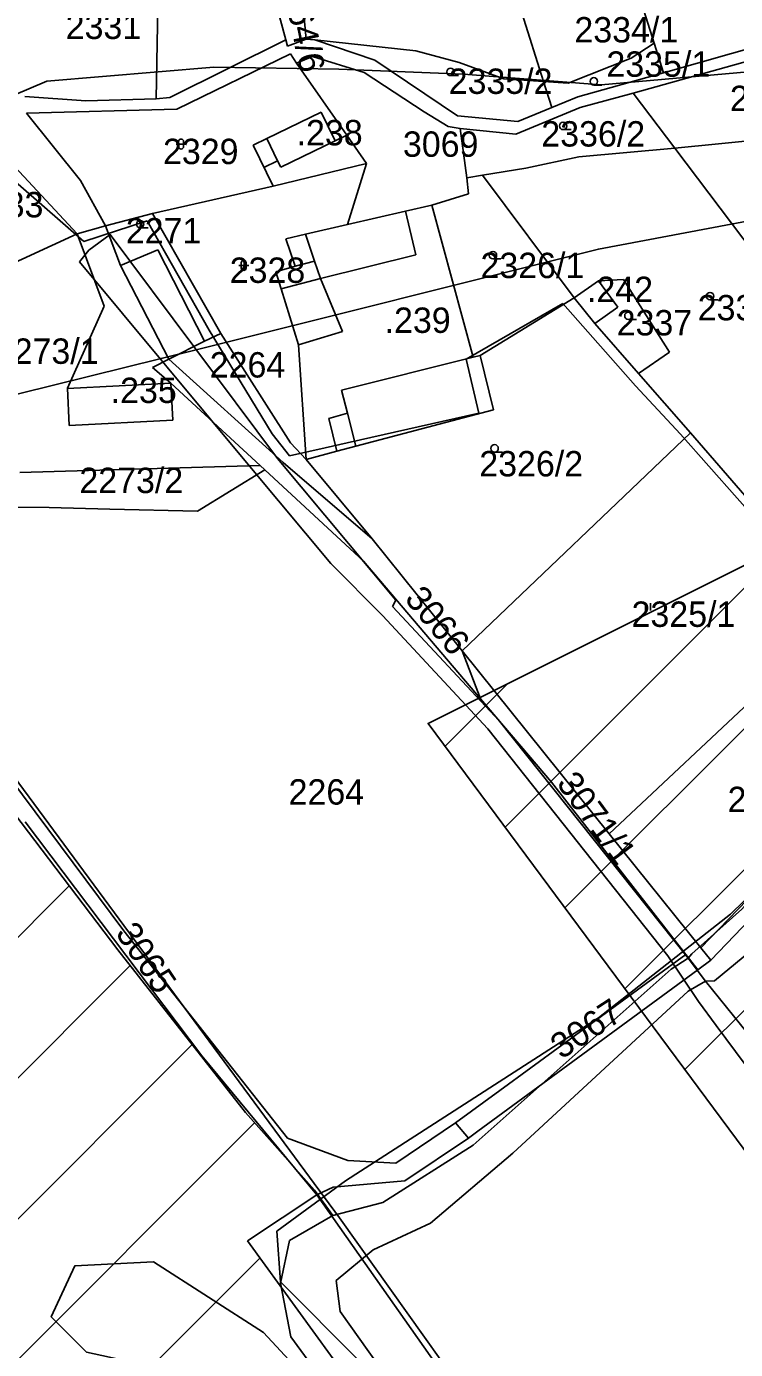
# Model space of a CAD drawing. Extents: x -564810 to -550519, y -1045831 to -1034011.
# Drawn here: x -553011.6 to -552869.1, y -1036898.7 to -1036632.8 of the extents above; entities that cross this region are included whole.
import ezdxf

# ---------------------------------------------------------------- set-up
doc = ezdxf.new("R2010")
doc.units = 0
for name, color, linetype in [('KN stav', 7, 'Continuous'), ('Lesní porost', 7, 'Continuous'), ('Obvod KPU', 7, 'Continuous'), ('Odvodněné plochy', 7, 'Continuous'), ('Parcelní čísla', 7, 'Continuous'), ('Polní cesty stavající', 7, 'Continuous'), ('přeložka st silnice', 7, 'Continuous'), ('STG', 7, 'Continuous'), ('vodní toky', 7, 'Continuous'), ('Vrstva 22', 7, 'Continuous'), ('Vrstva 33', 7, 'Continuous'), ('Vrstva 4', 7, 'Continuous'), ('Vrstva 5', 7, 'Continuous'), ('zamokř ploch', 7, 'Continuous')]:
    doc.layers.add(name, color=color, linetype=linetype)

msp = doc.modelspace()

# ---------------------------------------------------------------- linework, layer by layer
at = {"layer": 'KN stav'}
for p, q in [((-552957.26, -1036615.94), (-552955.38, -1036635.35)), ((-552963.64, -1036619.89), (-552959.48, -1036635.45)), ((-552889.16, -1036624.42), (-552885.49, -1036636.1)), ((-552985.17, -1036628.73), (-552985.52, -1036647.32)), ((-552912.09, -1036630.06), (-552907.71, -1036643.85)), ((-552959.48, -1036635.45), (-552982.76, -1036647.02)), ((-552959.15, -1036636.7), (-552959.48, -1036635.45)), ((-552955.38, -1036635.35), (-552959.15, -1036636.7)), ((-552953.69, -1036635.47), (-552955.38, -1036635.35)), ((-552933.36, -1036637.65), (-552953.69, -1036635.47)), ((-552941.59, -1036639.51), (-552953.69, -1036635.47)), ((-552885.49, -1036636.1), (-552890.09, -1036639.11)), ((-552885.49, -1036636.1), (-552883.61, -1036642.07)), ((-552861.75, -1036635.89), (-552883.61, -1036642.07)), ((-552981.4, -1036649.36), (-552958.55, -1036638.25)), ((-552958.55, -1036638.25), (-552957.33, -1036640.15)), ((-552957.33, -1036640.15), (-552954.14, -1036638.82)), ((-552954.14, -1036638.82), (-552943.77, -1036642.01)), ((-552925, -1036650.72), (-552941.59, -1036639.51)), ((-552924.65, -1036639.99), (-552933.36, -1036637.65)), ((-552915.7, -1036643.3), (-552924.65, -1036639.99)), ((-552890.09, -1036639.11), (-552902.79, -1036644.19)), ((-552889.68, -1036646.16), (-552862.2, -1036638.49)), ((-552957.33, -1036640.15), (-552947.24, -1036654.58)), ((-552943.77, -1036642.01), (-552931.72, -1036649.92)), ((-552883.61, -1036642.07), (-552900.83, -1036646.94)), ((-552907.71, -1036643.85), (-552915.7, -1036643.3)), ((-552907.71, -1036643.85), (-552906.06, -1036649.07)), ((-552902.79, -1036644.19), (-552907.71, -1036643.85)), ((-552999.69, -1036647.72), (-553011.94, -1036646.87)), ((-552985.52, -1036647.32), (-552999.69, -1036647.72)), ((-552982.76, -1036647.02), (-552985.52, -1036647.32)), ((-552900.83, -1036646.94), (-552906.06, -1036649.07)), ((-552900.36, -1036649.04), (-552889.68, -1036646.16)), ((-552889.68, -1036646.16), (-552881.33, -1036657.22)), ((-553011.59, -1036650.17), (-552981.4, -1036649.36)), ((-553000.75, -1036663.71), (-553011.59, -1036650.17)), ((-552952.39, -1036649.97), (-552963.32, -1036655.27)), ((-552949.6, -1036655.73), (-552952.39, -1036649.97)), ((-552931.72, -1036649.92), (-552926.89, -1036652.9)), ((-552913.26, -1036654.38), (-552900.36, -1036649.04)), ((-552906.06, -1036649.07), (-552912.9, -1036651.85)), ((-552926.89, -1036652.9), (-552924.46, -1036653.28)), ((-552912.9, -1036651.85), (-552925, -1036650.72)), ((-552924.46, -1036653.28), (-552923.15, -1036663.19)), ((-552924.46, -1036653.28), (-552913.26, -1036654.38)), ((-552963.32, -1036655.27), (-552966.06, -1036656.6)), ((-552947.24, -1036654.58), (-552949.6, -1036655.73)), ((-552947.24, -1036654.58), (-552943.26, -1036660.28)), ((-552853.82, -1036654.46), (-552881.33, -1036657.22)), ((-553017.54, -1036657.15), (-553001.41, -1036674.42)), ((-553001.41, -1036674.42), (-553017.54, -1036657.15)), ((-552966.06, -1036656.6), (-552962.05, -1036664.87)), ((-552881.33, -1036657.22), (-552900.64, -1036658.94)), ((-552881.33, -1036657.22), (-552855.3, -1036691.72)), ((-552962.05, -1036664.87), (-552943.26, -1036660.28)), ((-552943.26, -1036660.28), (-552947.09, -1036672.57)), ((-552911.26, -1036661.27), (-552919.98, -1036662.68)), ((-552900.64, -1036658.94), (-552911.26, -1036661.27)), ((-552995.74, -1036672.81), (-553000.75, -1036663.71)), ((-552923.15, -1036663.19), (-552919.98, -1036662.68)), ((-552923.15, -1036663.19), (-552922.82, -1036666.42)), ((-552919.98, -1036662.68), (-552901.58, -1036687.28)), ((-552962.05, -1036664.87), (-552986.29, -1036670.37)), ((-552922.82, -1036666.42), (-552930.17, -1036668.66)), ((-552935.45, -1036669.88), (-552930.17, -1036668.66)), ((-552930.17, -1036668.66), (-552921.84, -1036699.25)), ((-552986.29, -1036670.37), (-552995.74, -1036672.81)), ((-552986.29, -1036670.37), (-552972.56, -1036694.45)), ((-552947.09, -1036672.57), (-552935.45, -1036669.88)), ((-553001.41, -1036674.42), (-553034.02, -1036689.47)), ((-553034.02, -1036689.47), (-553001.41, -1036674.42)), ((-553001.41, -1036674.42), (-552995.74, -1036672.81)), ((-553001.41, -1036674.42), (-552995.95, -1036689.01)), ((-552995.74, -1036672.81), (-552992.72, -1036680.83)), ((-552955.54, -1036674.52), (-552959.47, -1036675.43)), ((-552947.09, -1036672.57), (-552955.54, -1036674.52)), ((-552959.47, -1036675.43), (-552957.61, -1036680.91)), ((-552992.72, -1036680.83), (-552985.21, -1036677.67)), ((-552985.21, -1036677.67), (-552975.8, -1036695.99)), ((-552957.61, -1036680.91), (-552961.47, -1036682.1)), ((-552961.47, -1036682.1), (-552960.41, -1036685.5)), ((-552896.68, -1036683.9), (-552901.58, -1036687.28)), ((-552891.64, -1036683.61), (-552896.68, -1036683.9)), ((-552896.68, -1036683.9), (-552892.78, -1036689.18)), ((-552882.38, -1036698.21), (-552891.64, -1036683.61)), ((-552960.41, -1036685.5), (-552956.92, -1036696.74)), ((-552920.46, -1036698.9), (-552901.58, -1036687.28)), ((-552901.58, -1036687.28), (-552897.39, -1036692.45)), ((-552995.95, -1036689.01), (-553003.37, -1036705.45)), ((-552892.78, -1036689.18), (-552897.39, -1036692.45)), ((-552897.39, -1036692.45), (-552888.64, -1036702.49)), ((-552972.56, -1036694.45), (-552975.8, -1036695.99)), ((-552958.52, -1036716.43), (-552972.56, -1036694.45)), ((-552975.8, -1036695.99), (-552982.97, -1036699.63)), ((-552956.92, -1036696.74), (-552955.37, -1036719.76)), ((-552888.64, -1036702.49), (-552882.38, -1036698.21)), ((-552982.97, -1036699.63), (-552986.24, -1036701.29)), ((-552982.97, -1036699.63), (-552959.99, -1036720.4)), ((-552921.84, -1036699.25), (-552920.46, -1036698.9)), ((-552920.46, -1036698.9), (-552917.74, -1036709.8)), ((-552986.24, -1036701.29), (-552982.56, -1036704.47)), ((-552888.64, -1036702.49), (-552878.21, -1036714.46)), ((-553003.37, -1036705.45), (-553003, -1036712.94)), ((-552982.19, -1036711.9), (-552982.56, -1036704.47)), ((-552982.56, -1036704.47), (-552964.61, -1036721.02)), ((-552917.74, -1036709.8), (-552945.39, -1036717.12)), ((-553003, -1036712.94), (-552982.19, -1036711.9)), ((-552955.37, -1036719.76), (-552958.52, -1036716.43)), ((-552878.21, -1036714.46), (-552924.04, -1036758.24)), ((-552878.21, -1036714.46), (-552863.3, -1036731.56)), ((-552949.23, -1036718.14), (-552955.37, -1036719.76)), ((-552942.13, -1036735.71), (-552955.37, -1036719.76)), ((-552945.39, -1036717.12), (-552949.23, -1036718.14)), ((-552964.61, -1036721.02), (-553012.94, -1036722.42)), ((-552963.73, -1036721.84), (-552977.2, -1036730.2)), ((-552963.73, -1036721.84), (-552964.61, -1036721.02)), ((-552943.85, -1036740.22), (-552963.73, -1036721.84)), ((-552959.99, -1036720.4), (-552942.13, -1036735.71)), ((-553035.83, -1036729.19), (-553007, -1036729.44)), ((-552994.87, -1036729.75), (-553007, -1036729.44)), ((-552977.2, -1036730.2), (-552994.87, -1036729.75)), ((-552942.13, -1036735.71), (-552924.04, -1036758.24)), ((-552920.37, -1036767.87), (-552943.85, -1036740.22)), ((-553044.87, -1036743.82), (-552992.06, -1036814.49)), ((-552847.39, -1036750.74), (-552894.52, -1036795.01)), ((-552924.04, -1036758.24), (-552920.37, -1036767.87)), ((-552924.04, -1036758.24), (-552894.52, -1036795.01)), ((-552906.11, -1036784.67), (-552920.37, -1036767.87)), ((-552879.12, -1036819.3), (-552906.11, -1036784.67)), ((-553011.86, -1036792.61), (-552976.39, -1036839.66)), ((-552976.39, -1036839.66), (-553011.86, -1036792.61)), ((-552894.52, -1036795.01), (-552876.14, -1036817.91)), ((-552854.93, -1036796), (-552876.14, -1036817.91)), ((-552854.06, -1036799.49), (-552874.11, -1036820.43)), ((-552992.06, -1036814.49), (-552959.16, -1036856.18)), ((-552876.14, -1036817.91), (-552874.11, -1036820.43)), ((-552916.49, -1036846.59), (-552879.12, -1036819.3)), ((-552879.12, -1036819.3), (-552876.74, -1036822.36)), ((-552874.11, -1036820.43), (-552876.74, -1036822.36)), ((-552876.74, -1036822.36), (-552920.89, -1036854.79)), ((-552976.39, -1036839.66), (-552953.24, -1036867.58)), ((-552953.24, -1036867.58), (-552976.39, -1036839.66)), ((-552925.41, -1036853.11), (-552916.49, -1036846.59)), ((-552937.36, -1036861.22), (-552925.41, -1036853.11)), ((-552925.41, -1036853.11), (-552922.78, -1036856.18)), ((-552920.89, -1036854.79), (-552922.78, -1036856.18)), ((-552959.16, -1036856.18), (-552947, -1036860.67)), ((-552922.78, -1036856.18), (-552935.6, -1036864.73)), ((-552947, -1036860.67), (-552937.36, -1036861.22)), ((-552935.6, -1036864.73), (-552949.96, -1036866.05)), ((-552953.24, -1036867.58), (-552967.16, -1036876.79)), ((-552967.16, -1036876.79), (-552953.24, -1036867.58)), ((-552949.96, -1036866.05), (-552953.24, -1036867.58)), ((-552953.24, -1036867.58), (-552842.6, -1037024.79)), ((-552967.16, -1036876.79), (-552909.89, -1036955.71)), ((-552909.89, -1036955.71), (-552967.16, -1036876.79))]:
    msp.add_line(p, q, dxfattribs=at)
at = {"layer": 'Lesní porost'}
for p, q in [((-553082.6, -1036885.05), (-553003, -1036805.46)), ((-553071.01, -1036901.75), (-552990.73, -1036821.47)), ((-553059.41, -1036918.44), (-552978.32, -1036837.34)), ((-553047.82, -1036935.13), (-552965.78, -1036853.08)), ((-553036.23, -1036951.82), (-552964.65, -1036880.24))]:
    msp.add_line(p, q, dxfattribs=at)
msp.add_lwpolyline([(-553146.64, -1036727.62), (-553139.68, -1036718.33), (-553129.51, -1036716.88), (-553121.51, -1036717.92), (-553113.12, -1036715.47), (-553098.36, -1036708.87), (-553083.05, -1036699.3), (-553078.09, -1036714.1), (-553071.17, -1036716.95), (-553043.41, -1036752.8), (-553036.17, -1036762.13), (-553020.94, -1036781.92), (-552993.21, -1036818.31), (-552967.61, -1036851.02), (-552953.72, -1036866.65), (-552950.02, -1036871.7), (-552958.74, -1036876.77), (-552960.54, -1036885.34), (-552958.5, -1036896.1), (-552948.99, -1036909.12)], dxfattribs=at)
at = {"layer": 'Obvod KPU'}
for p, q in [((-553000.04, -1036675.95), (-553018.55, -1036659.94)), ((-552987.32, -1036671.82), (-553000.04, -1036675.95)), ((-552974.88, -1036693.82), (-552987.32, -1036671.82)), ((-552903.86, -1036688.45), (-552923.24, -1036699.61)), ((-552889.25, -1036705), (-552903.86, -1036688.45)), ((-552962.23, -1036714.66), (-552974.88, -1036693.82)), ((-552923.24, -1036699.61), (-552920.71, -1036710.45)), ((-552880.17, -1036714.7), (-552889.25, -1036705)), ((-552920.71, -1036710.45), (-552947.16, -1036716.46)), ((-552958.74, -1036719.05), (-552962.23, -1036714.66)), ((-552947.16, -1036716.46), (-552951.58, -1036717.43)), ((-552861.65, -1036735.71), (-552880.17, -1036714.7)), ((-552951.58, -1036717.43), (-552958.74, -1036719.05))]:
    msp.add_line(p, q, dxfattribs=at)
at = {"layer": 'Odvodněné plochy'}
msp.add_lwpolyline([(-552687.96, -1037100.5), (-552930.89, -1036772.83), (-552794.7, -1036704.72), (-552792.14, -1036703.83), (-552782.15, -1036704.4), (-552765.68, -1036725.64), (-552743.84, -1036752.03), (-552724.66, -1036770.5), (-552706.61, -1036793.91), (-552696.62, -1036807.49), (-552698.04, -1036810.04), (-552692.79, -1036817.44), (-552723.94, -1036856.6), (-552638.53, -1036945.5)], dxfattribs=at)
at = {"layer": 'Polní cesty stavající'}
for p, q in [((-553000.91, -1036680.07), (-552999.09, -1036677.73)), ((-552999.09, -1036677.73), (-553000.91, -1036680.07)), ((-553000.91, -1036680.07), (-552966.05, -1036721.98)), ((-552937.4, -1036748.07), (-552961.15, -1036719.6)), ((-552966.05, -1036721.98), (-552950.46, -1036740.72)), ((-552950.46, -1036740.72), (-552940.09, -1036751.17)), ((-552938.07, -1036749.34), (-552937.4, -1036748.07)), ((-552940.09, -1036751.17), (-552918.88, -1036773.95)), ((-552916.57, -1036772.4), (-552938.07, -1036749.34)), ((-552878.67, -1036820.01), (-552916.57, -1036772.4)), ((-552918.88, -1036773.95), (-552882.75, -1036819.55)), ((-552882.75, -1036819.55), (-552876.58, -1036828.71)), ((-552875.18, -1036824.6), (-552878.67, -1036820.01)), ((-552866.74, -1036835.06), (-552875.18, -1036824.6)), ((-552876.58, -1036828.71), (-552873.03, -1036833.57)), ((-552873.03, -1036833.57), (-552859.35, -1036851.96))]:
    msp.add_line(p, q, dxfattribs=at)
msp.add_lwpolyline([(-552961.15, -1036719.6), (-552994.76, -1036674.59), (-552999.09, -1036677.73)], dxfattribs=at)
at = {"layer": 'přeložka st silnice'}
for p, q in [((-552903.4, -1036809.91), (-552801.72, -1036708.23)), ((-552891.35, -1036826.15), (-552776.67, -1036711.47)), ((-552879.31, -1036842.39), (-552764.27, -1036727.35)), ((-552915.44, -1036793.66), (-552858.3, -1036736.53)), ((-552927.48, -1036777.42), (-552914.88, -1036764.82))]:
    msp.add_line(p, q, dxfattribs=at)
at = {"layer": 'STG'}
msp.add_lwpolyline([(-553086.83, -1037509.03), (-553102.44, -1037299.55), (-553086.83, -1037209.51), (-553071.21, -1037131.41), (-553050.08, -1037031.26), (-553047.33, -1036952.24), (-553054.68, -1036883.33), (-553078.56, -1036837.39), (-553119.89, -1036809.83), (-553157.55, -1036794.21), (-553196.13, -1036789.62), (-553152.96, -1036760.21), (-553125.41, -1036746.43), (-553070.29, -1036720.71), (-552977.52, -1036697.74), (-552896.69, -1036677.52), (-552848, -1036668.34), (-552776.36, -1036649.96), (-552684.5, -1036608.61), (-552638.57, -1036588.4), (-552609.18, -1036560.84), (-552571.52, -1036514.9), (-552546.72, -1036489.17)], dxfattribs=at)
at = {"layer": 'vodní toky'}
for points in [[(-552937.05, -1036907.22), (-552948.58, -1036890.99), (-552949.39, -1036884.8), (-552941.93, -1036878.63), (-552930.43, -1036873.28), (-552913.88, -1036859.22), (-552878.63, -1036826.63), (-552875.18, -1036824.6), (-552873.39, -1036824.55), (-552857.66, -1036811.58), (-552848.48, -1036798), (-552826.04, -1036770.47), (-552809.46, -1036757.3), (-552786.31, -1036738.05), (-552780.34, -1036732.82), (-552772.03, -1036720.92), (-552772.21, -1036709.87), (-552784.1, -1036693.86), (-552784.98, -1036694.67), (-552787.38, -1036696.5)], [(-552787.38, -1036696.5), (-552778.67, -1036706.62), (-552776.59, -1036712.1), (-552777.66, -1036720.41), (-552784.89, -1036729.31), (-552813.96, -1036753.87), (-552832.14, -1036769.74), (-552852.32, -1036792.52), (-552867.89, -1036810.15), (-552877.89, -1036819.14), (-552878.67, -1036820.01), (-552882.09, -1036822.22), (-552921.84, -1036857.59), (-552939.98, -1036869.11), (-552950.02, -1036871.7), (-552958.74, -1036876.77), (-552960.54, -1036885.34), (-552958.5, -1036896.1), (-552948.99, -1036909.12)]]:
    msp.add_lwpolyline(points, dxfattribs=at)
at = {"layer": 'Vrstva 33'}
for points in [[(-552896.64, -1036832.02), (-552870.12, -1036811.16), (-552837.42, -1036779.18), (-552809.09, -1036744.29), (-552783.66, -1036724.66), (-552767.68, -1036700.67), (-552758.23, -1036681.34), (-552737.16, -1036648.63), (-552719, -1036601.38), (-552705.2, -1036538.15), (-552687.76, -1036536.69), (-552655.06, -1036539.6), (-552633.27, -1036541.05), (-552585.32, -1036444.38), (-552563.52, -1036392.48), (-552511.94, -1036348.14), (-552488.69, -1036314.71), (-552549.72, -1036441.91)], [(-553163.92, -1036709.85), (-553122.95, -1036708.79), (-553110.6, -1036706.32), (-553092.94, -1036699.61), (-553080.23, -1036692.19), (-553043.86, -1036658.98), (-553030.09, -1036653.33), (-553007.49, -1036643.79), (-552973.94, -1036640.96), (-552948.87, -1036641.32), (-552923.8, -1036642.38), (-552896.11, -1036644.5), (-552848.44, -1036640.26), (-552837.85, -1036639.9), (-552831.14, -1036643.44), (-552817.02, -1036631.43), (-552737.21, -1036583.84), (-552724.5, -1036572.89), (-552717.44, -1036555.58), (-552705.2, -1036538.15)], [(-552944.59, -1036901.07), (-552960.57, -1036885.08), (-552961.3, -1036874.9), (-552947.5, -1036864.73), (-552896.64, -1036832.02)], [(-552868.3, -1037043.25), (-552878.76, -1037022.38), (-552893.75, -1037001.06), (-552922.17, -1036967.11), (-552933.21, -1036949.74), (-552943.47, -1036917.37), (-552963.99, -1036895.26), (-552986.09, -1036881.05), (-553001.88, -1036881.84), (-553006.61, -1036892.1), (-552999.51, -1036899.21), (-552981.36, -1036903.15), (-552971.1, -1036924.47), (-552951.37, -1036945.79), (-552937.16, -1036963.16), (-552922.95, -1036999.48), (-552920.59, -1037032.64), (-552913.48, -1037061.85), (-552904.01, -1037067.38), (-552888.23, -1037062.64), (-552866.12, -1037067.96)]]:
    msp.add_lwpolyline(points, dxfattribs=at)
at = {"layer": 'Vrstva 4'}
for p, q in [((-552963.32, -1036655.27), (-552961.14, -1036659.75)), ((-552960.52, -1036661.02), (-552949.6, -1036655.72)), ((-552963.89, -1036661.08), (-552961.14, -1036659.75)), ((-552961.14, -1036659.75), (-552960.52, -1036661.02)), ((-552933.4, -1036678.65), (-552935.45, -1036669.87)), ((-552955.54, -1036674.52), (-552953.7, -1036679.91)), ((-552952.49, -1036683.45), (-552933.4, -1036678.65)), ((-552992.72, -1036680.83), (-552982.97, -1036699.63)), ((-552957.61, -1036680.91), (-552953.7, -1036679.91)), ((-552953.7, -1036679.91), (-552952.49, -1036683.45)), ((-552952.49, -1036683.45), (-552960.42, -1036685.49)), ((-552948.13, -1036694.09), (-552952.49, -1036683.45)), ((-552956.92, -1036696.74), (-552948.13, -1036694.09)), ((-552948.28, -1036705.87), (-552921.84, -1036699.24)), ((-553003.37, -1036705.51), (-552982.56, -1036704.47)), ((-552947.09, -1036710.49), (-552948.28, -1036705.87)), ((-552950.84, -1036711.57), (-552947.09, -1036710.49)), ((-552949.23, -1036718.13), (-552950.84, -1036711.57)), ((-552945.39, -1036717.12), (-552947.09, -1036710.49))]:
    msp.add_line(p, q, dxfattribs=at)
at = {"layer": 'Vrstva 5'}
msp.add_lwpolyline([(-553153.82, -1036717.79), (-553120.78, -1036720.53), (-553077.61, -1036697.47), (-552948.67, -1036872.18), (-552799.53, -1037081.76), (-552742.11, -1037143.32), (-552838.62, -1037227.28), (-552866, -1037405.86)], dxfattribs=at)
at = {"layer": 'zamokř ploch'}
for p, q in [((-552926.41, -1036642.65), (-552924.81, -1036642.65)), ((-552897.6, -1036644.55), (-552896, -1036644.55)), ((-552981.03, -1036655.9), (-552981.03, -1036656.9)), ((-552980.03, -1036655.9), (-552980.03, -1036656.9)), ((-552903.78, -1036653.5), (-552902.18, -1036653.5)), ((-552981.53, -1036656.4), (-552979.53, -1036656.4)), ((-552988.74, -1036673.24), (-552987.14, -1036673.24)), ((-552917.88, -1036679.49), (-552916.28, -1036679.49)), ((-552968.95, -1036680.79), (-552966.95, -1036680.79)), ((-552968.45, -1036680.29), (-552968.45, -1036681.29)), ((-552967.45, -1036680.29), (-552967.45, -1036681.29)), ((-552874.26, -1036687.71), (-552872.66, -1036687.71)), ((-552890.66, -1036691.66), (-552889.06, -1036691.66)), ((-552917.55, -1036718.31), (-552915.95, -1036718.31)), ((-552887.23, -1036748.67), (-552887.23, -1036750.17)), ((-552886.23, -1036748.67), (-552886.23, -1036750.17))]:
    msp.add_line(p, q, dxfattribs=at)
for centre in [(-552926.41, -1036641.9), (-552897.6, -1036643.8), (-552903.78, -1036652.75), (-552988.74, -1036672.49), (-552917.88, -1036678.74), (-552874.26, -1036686.96), (-552890.66, -1036690.91), (-552917.55, -1036717.56)]:
    msp.add_circle(centre, 0.75, dxfattribs=at)
for centre, start, end in [((-552980.53, -1036655.9), 0, 180), ((-552980.53, -1036656.9), 180, 0), ((-552967.95, -1036680.29), 0, 180), ((-552967.95, -1036681.29), 180, 0)]:
    msp.add_arc(centre, 0.5, start, end, dxfattribs=at)

# ---------------------------------------------------------------- texts
at = {"layer": 'Parcelní čísla'}
for s, rotation, p in [('3064/6', 281.4814, (-552960.67, -1036621.87)), ('3066', 309.8336, (-552935.8, -1036747.9)), ('3071/1', 306.4075, (-552905.25, -1036784.92)), ('3065', 303.9509, (-552993.84, -1036814.99)), ('3067', 33.3524, (-552904.11, -1036840.45))]:
    msp.add_text(s, height=5.1, rotation=rotation, dxfattribs=at).set_placement(p)
for s, p in [('2331', (-553003.71, -1036635.29)), ('2334/1', (-552901.51, -1036635.98)), ('2335/1', (-552895.08, -1036642.88)), ('2335/2', (-552926.77, -1036646.32)), ('2336/1', (-552870.27, -1036649.77)), ('2336/2', (-552908.16, -1036656.9)), ('2329', (-552984.16, -1036660.43)), ('3069', (-552935.96, -1036658.96)), ('2271', (-552991.63, -1036676.37)), ('2328', (-552970.76, -1036684.3)), ('2326/1', (-552920.38, -1036683.34)), ('2338/2', (-552876.74, -1036691.83)), ('2337', (-552893.02, -1036694.86)), ('2273/1', (-553017.96, -1036700.57)), ('2264', (-552974.77, -1036703.32)), ('2326/2', (-552920.62, -1036723.19)), ('2273/2', (-553000.96, -1036726.54)), ('2325/1', (-552890.03, -1036753.43)), ('2264', (-552958.93, -1036789.15)), ('2325/2', (-552870.74, -1036790.66))]:
    msp.add_text(s, height=5.1, dxfattribs=at).set_placement(p)
at = {"layer": 'Vrstva 22'}
for s, p in [('.238', (-552957.32, -1036656.66)), ('.233', (-553021.46, -1036671.13)), ('.242', (-552898.98, -1036688.15)), ('.239', (-552939.64, -1036694.35)), ('.235', (-552994.67, -1036708.44))]:
    msp.add_text(s, height=5.1, dxfattribs=at).set_placement(p)

doc.saveas('drawing.dxf')
